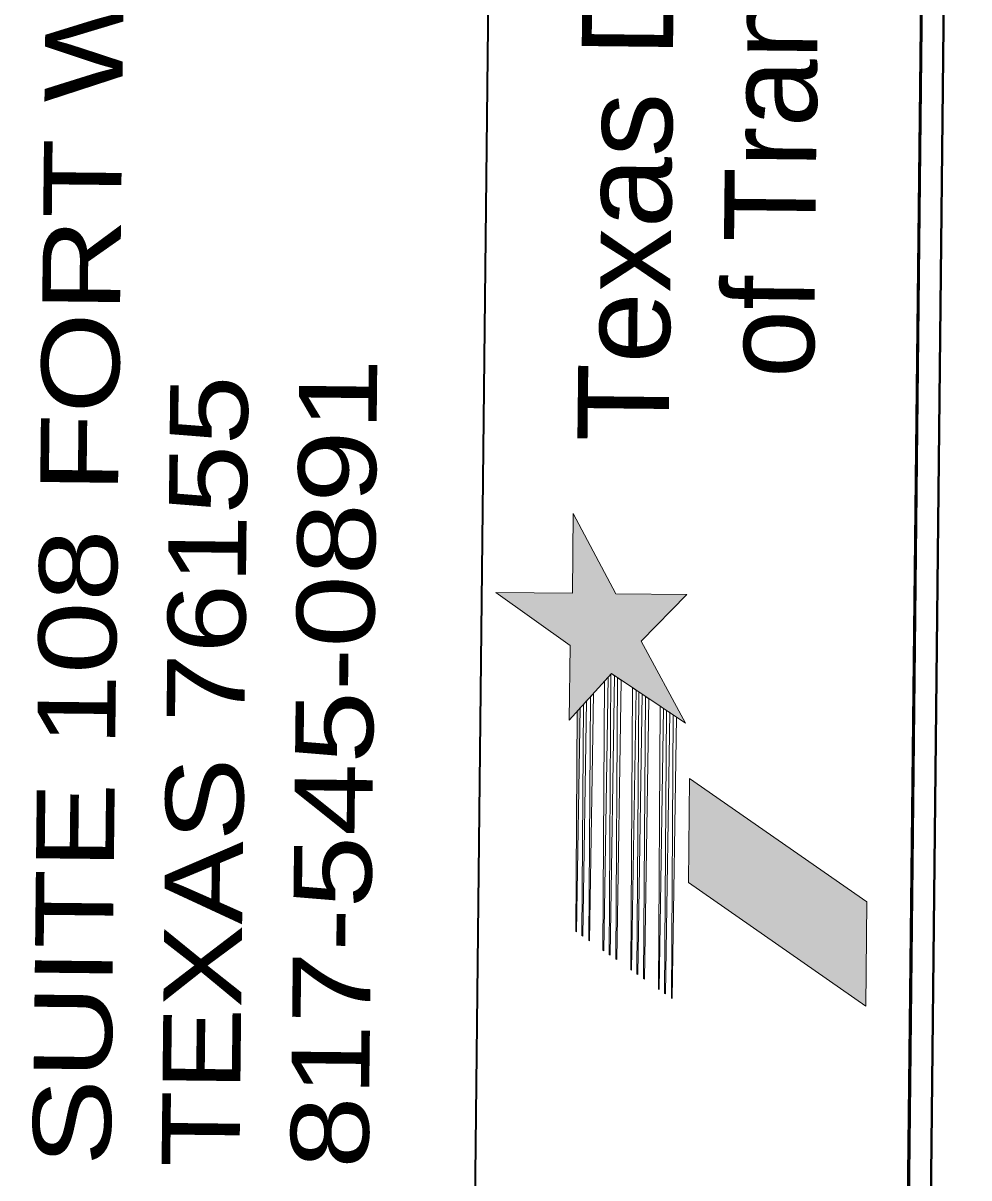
# Model space of a CAD drawing. Extents: x 2356576 to 2377878, y 6966390 to 6990634.
# Drawn here: x 2366949.5 to 2367163.6, y 6989801.8 to 6990063.3 of the extents above; entities that cross this region are included whole.
import ezdxf
from ezdxf.enums import TextEntityAlignment as Align

# ---------------------------------------------------------------- set-up
doc = ezdxf.new("R2010")
doc.units = 0
doc.header["$LTSCALE"] = 7.1
doc.layers.add('19', color=7, linetype='Continuous', lineweight=13)
doc.layers.add('8', color=7, linetype='Continuous', lineweight=13)

msp = doc.modelspace()

# ---------------------------------------------------------------- hatches: boundary and pattern name
at = {"layer": '19'}
for points in [[(2367056.576, 6989934.359), (2367073.336, 6989922.377), (2367073.15, 6989905.471), (2367082.696, 6989915.993), (2367099.486, 6989904.803), (2367089.458, 6989923.369), (2367099.81, 6989933.879), (2367083.682, 6989934.057), (2367074.076, 6989952.247), (2367073.88, 6989934.167)], [(2367074.618, 6989857.651), (2367074.954, 6989907.439), (2367075.64, 6989908.231), (2367074.828, 6989857.539)], [(2367100.132, 6989868.697), (2367140.286, 6989840.721), (2367140.548, 6989864.305), (2367100.388, 6989892.265)]]:
    msp.add_hatch(color=256, dxfattribs=at).paths.add_polyline_path(points)
at = {"layer": '8'}
for points in [[(2367056.576, 6989934.359), (2367073.336, 6989922.377), (2367073.15, 6989905.471), (2367082.696, 6989915.993), (2367099.486, 6989904.803), (2367089.458, 6989923.369), (2367099.81, 6989933.879), (2367083.682, 6989934.057), (2367074.076, 6989952.247), (2367073.88, 6989934.167)], [(2367074.618, 6989857.651), (2367074.954, 6989907.439), (2367075.64, 6989908.231), (2367074.828, 6989857.539)], [(2367100.132, 6989868.697), (2367140.286, 6989840.721), (2367140.548, 6989864.305), (2367100.388, 6989892.265)]]:
    msp.add_hatch(color=256, dxfattribs=at).paths.add_polyline_path(points)

# ---------------------------------------------------------------- linework, layer by layer
at = {"layer": '19', "lineweight": 35}
for p, q in [((2367158.576, 6990592.767), (2367149.612, 6989785.553)), ((2367056.942, 6990259.323), (2367051.692, 6989786.641))]:
    msp.add_line(p, q, dxfattribs=at)
at = {"layer": '19', "lineweight": 40}
msp.add_lwpolyline([(2363758.773, 6990629.355), (2367158.576, 6990592.767), (2366922.891, 6968646.236), (2363523.088, 6968682.826)], close=True, dxfattribs=at)
at = {"layer": '19'}
for points in [[(2367056.576, 6989934.359), (2367073.336, 6989922.377), (2367073.15, 6989905.471), (2367082.696, 6989915.993), (2367099.486, 6989904.803), (2367089.458, 6989923.369), (2367099.81, 6989933.879), (2367083.682, 6989934.057), (2367074.076, 6989952.247), (2367073.88, 6989934.167)], [(2367080.78, 6989853.367), (2367081.142, 6989914.273), (2367081.958, 6989915.149), (2367080.982, 6989853.247)], [(2367082.182, 6989852.369), (2367082.558, 6989915.803), (2367082.696, 6989915.979), (2367083.402, 6989915.505), (2367082.4, 6989852.259)], [(2367083.714, 6989851.329), (2367084.12, 6989915.049), (2367084.94, 6989914.495), (2367083.914, 6989851.237)], [(2367077.566, 6989855.595), (2367077.94, 6989910.739), (2367078.648, 6989911.513), (2367077.76, 6989855.503)], [(2367087.072, 6989848.977), (2367087.5, 6989912.797), (2367088.288, 6989912.269), (2367087.258, 6989848.857)], [(2367088.472, 6989847.973), (2367088.908, 6989911.843), (2367089.68, 6989911.333), (2367088.668, 6989847.881)], [(2367076.04, 6989856.663), (2367076.372, 6989909.015), (2367077.098, 6989909.801), (2367076.218, 6989856.527)], [(2367089.988, 6989846.939), (2367090.424, 6989910.831), (2367091.204, 6989910.305), (2367090.202, 6989846.821)], [(2367074.618, 6989857.651), (2367074.954, 6989907.439), (2367075.64, 6989908.231), (2367074.828, 6989857.539)], [(2367093.356, 6989844.587), (2367093.778, 6989908.599), (2367094.522, 6989908.097), (2367093.552, 6989844.467)], [(2367094.736, 6989843.589), (2367095.188, 6989907.667), (2367095.922, 6989907.167), (2367094.95, 6989843.477)], [(2367096.276, 6989842.555), (2367096.7, 6989906.647), (2367097.448, 6989906.133), (2367096.452, 6989842.425)], [(2367100.132, 6989868.697), (2367140.286, 6989840.721), (2367140.548, 6989864.305), (2367100.388, 6989892.265)]]:
    msp.add_lwpolyline(points, close=True, dxfattribs=at)
at = {"layer": '8', "lineweight": 35}
for p, q in [((2367158.576, 6990592.767), (2367149.612, 6989785.553)), ((2367056.942, 6990259.323), (2367051.692, 6989786.641))]:
    msp.add_line(p, q, dxfattribs=at)
at = {"layer": '8', "lineweight": 40}
for points in [[(2363753.827, 6990634.409), (2367163.63, 6990597.713), (2366927.837, 6968641.182), (2363518.034, 6968677.88)], [(2363758.773, 6990629.355), (2367158.576, 6990592.767), (2366922.891, 6968646.236), (2363523.088, 6968682.826)]]:
    msp.add_lwpolyline(points, close=True, dxfattribs=at)
at = {"layer": '8'}
for points in [[(2367056.576, 6989934.359), (2367073.336, 6989922.377), (2367073.15, 6989905.471), (2367082.696, 6989915.993), (2367099.486, 6989904.803), (2367089.458, 6989923.369), (2367099.81, 6989933.879), (2367083.682, 6989934.057), (2367074.076, 6989952.247), (2367073.88, 6989934.167)], [(2367080.78, 6989853.367), (2367081.142, 6989914.273), (2367081.958, 6989915.149), (2367080.982, 6989853.247)], [(2367082.182, 6989852.369), (2367082.558, 6989915.803), (2367082.696, 6989915.979), (2367083.402, 6989915.505), (2367082.4, 6989852.259)], [(2367083.714, 6989851.329), (2367084.12, 6989915.049), (2367084.94, 6989914.495), (2367083.914, 6989851.237)], [(2367077.566, 6989855.595), (2367077.94, 6989910.739), (2367078.648, 6989911.513), (2367077.76, 6989855.503)], [(2367087.072, 6989848.977), (2367087.5, 6989912.797), (2367088.288, 6989912.269), (2367087.258, 6989848.857)], [(2367088.472, 6989847.973), (2367088.908, 6989911.843), (2367089.68, 6989911.333), (2367088.668, 6989847.881)], [(2367076.04, 6989856.663), (2367076.372, 6989909.015), (2367077.098, 6989909.801), (2367076.218, 6989856.527)], [(2367089.988, 6989846.939), (2367090.424, 6989910.831), (2367091.204, 6989910.305), (2367090.202, 6989846.821)], [(2367074.618, 6989857.651), (2367074.954, 6989907.439), (2367075.64, 6989908.231), (2367074.828, 6989857.539)], [(2367093.356, 6989844.587), (2367093.778, 6989908.599), (2367094.522, 6989908.097), (2367093.552, 6989844.467)], [(2367094.736, 6989843.589), (2367095.188, 6989907.667), (2367095.922, 6989907.167), (2367094.95, 6989843.477)], [(2367096.276, 6989842.555), (2367096.7, 6989906.647), (2367097.448, 6989906.133), (2367096.452, 6989842.425)], [(2367100.132, 6989868.697), (2367140.286, 6989840.721), (2367140.548, 6989864.305), (2367100.388, 6989892.265)]]:
    msp.add_lwpolyline(points, close=True, dxfattribs=at)

# ---------------------------------------------------------------- texts
at = {"layer": '19', "width": 1.05}
msp.add_text('Texas Department', height=20.67, rotation=89.364, dxfattribs=at).set_placement((2367096.99, 6990087.744), align=Align.CENTER)
at = {"layer": '19'}
msp.add_text('of Transportation', height=20.67, rotation=89.364, dxfattribs=at).set_placement((2367129.66, 6990087.304), align=Align.CENTER)
for s, width, p in [('SUITE 108 FORT WORTH , ', 1.25, (2366969.322, 6989804.453)), ('817-545-0891', 1.25, (2367027.688, 6989803.805)), ('TEXAS 76155', 1.2, (2366998.504, 6989804.129))]:
    msp.add_text(s, height=17.63, rotation=89.364, dxfattribs=dict(at, width=width)).set_placement(p)
at = {"layer": '8', "width": 1.05}
msp.add_text('Texas Department', height=20.67, rotation=89.364, dxfattribs=at).set_placement((2367096.99, 6990087.744), align=Align.CENTER)
at = {"layer": '8'}
msp.add_text('of Transportation', height=20.67, rotation=89.364, dxfattribs=at).set_placement((2367129.66, 6990087.304), align=Align.CENTER)
for s, width, p in [('SUITE 108 FORT WORTH , ', 1.25, (2366969.322, 6989804.453)), ('817-545-0891', 1.25, (2367027.688, 6989803.805)), ('TEXAS 76155', 1.2, (2366998.504, 6989804.129))]:
    msp.add_text(s, height=17.63, rotation=89.364, dxfattribs=dict(at, width=width)).set_placement(p)

doc.saveas('drawing.dxf')
